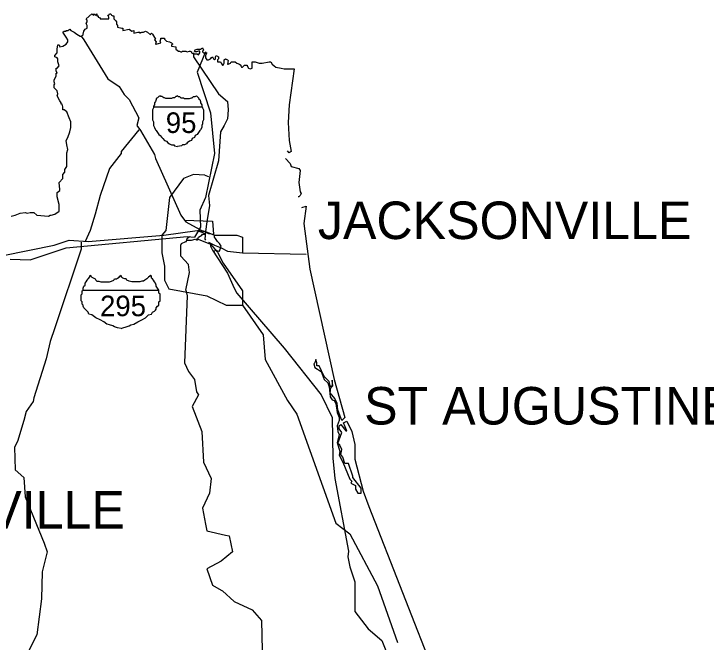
# Model space of a CAD drawing. Extents: x -820.2 to -798.1, y -2199.1 to -2182.2.
# Drawn here: x -806.07 to -805.24, y -2183.909 to -2183.155 of the extents above; entities that cross this region are included whole.
import ezdxf

# ---------------------------------------------------------------- set-up
doc = ezdxf.new("R2010")
doc.units = 0
for name, color, linetype in [('FLMap1', 7, 'Continuous'), ('FLMap2', 7, 'Continuous'), ('FLMap3', 7, 'Continuous'), ('TextMisc', 7, 'Continuous')]:
    doc.layers.add(name, color=color, linetype=linetype)

msp = doc.modelspace()

# ---------------------------------------------------------------- linework, layer by layer
at = {"layer": 'FLMap1'}
for p, q in [((-805.90286, -2183.26666), (-805.84382, -2183.26666)), ((-805.9872, -2183.48644), (-805.89641, -2183.48644))]:
    msp.add_line(p, q, dxfattribs=at)
for points in [[(-805.87408, -2183.25326), (-805.87508, -2183.25426), (-805.87607, -2183.25426), (-805.87756, -2183.25574), (-805.87855, -2183.25574), (-805.87954, -2183.25574), (-805.88103, -2183.25674), (-805.88202, -2183.25674), (-805.88351, -2183.25674), (-805.8845, -2183.25674), (-805.88698, -2183.25674), (-805.88798, -2183.25674), (-805.88946, -2183.25574), (-805.89046, -2183.25574), (-805.89294, -2183.25426), (-805.89393, -2183.25426), (-805.89492, -2183.25326), (-805.89641, -2183.25426), (-805.8979, -2183.25574), (-805.89939, -2183.25674), (-805.89939, -2183.25773), (-805.90038, -2183.26021), (-805.90137, -2183.2617), (-805.90137, -2183.26418), (-805.90286, -2183.26567), (-805.90286, -2183.26765), (-805.90385, -2183.27013), (-805.90385, -2183.27261), (-805.90385, -2183.27509), (-805.90385, -2183.27708), (-805.90385, -2183.27956), (-805.90385, -2183.28204), (-805.90286, -2183.28452), (-805.90286, -2183.287), (-805.90286, -2183.28899), (-805.90137, -2183.29147), (-805.90038, -2183.29395), (-805.89939, -2183.29494), (-805.8979, -2183.29742), (-805.89641, -2183.2999), (-805.89492, -2183.30089), (-805.89294, -2183.30337), (-805.89145, -2183.30437), (-805.88946, -2183.30685), (-805.88698, -2183.30784), (-805.8855, -2183.30982), (-805.88351, -2183.31081), (-805.88103, -2183.3123), (-805.87855, -2183.3123), (-805.87756, -2183.3133), (-805.87408, -2183.31429)], [(-805.87408, -2183.25326), (-805.8726, -2183.25426), (-805.8716, -2183.25426), (-805.87012, -2183.25574), (-805.86912, -2183.25574), (-805.86664, -2183.25574), (-805.86565, -2183.25674), (-805.86416, -2183.25674), (-805.86317, -2183.25674), (-805.86218, -2183.25674), (-805.86069, -2183.25674), (-805.8597, -2183.25674), (-805.85722, -2183.25574), (-805.85622, -2183.25574), (-805.85474, -2183.25426), (-805.85275, -2183.25426), (-805.85126, -2183.25326), (-805.85027, -2183.25426), (-805.84878, -2183.25574), (-805.84878, -2183.25674), (-805.84729, -2183.25773), (-805.8463, -2183.26021), (-805.8463, -2183.2617), (-805.84481, -2183.26418), (-805.84481, -2183.26567), (-805.84382, -2183.26765), (-805.84283, -2183.27013), (-805.84283, -2183.27261), (-805.84283, -2183.27509), (-805.84283, -2183.27708), (-805.84283, -2183.27956), (-805.84283, -2183.28204), (-805.84382, -2183.28452), (-805.84382, -2183.287), (-805.84481, -2183.28899), (-805.84481, -2183.29147), (-805.8463, -2183.29395), (-805.84729, -2183.29494), (-805.84878, -2183.29742), (-805.85027, -2183.2999), (-805.85275, -2183.30089), (-805.85374, -2183.30337), (-805.85622, -2183.30437), (-805.85722, -2183.30685), (-805.8597, -2183.30784), (-805.86218, -2183.30982), (-805.86317, -2183.31081), (-805.86565, -2183.3123), (-805.86813, -2183.3123), (-805.86912, -2183.3133), (-805.87408, -2183.31429)], [(-805.94156, -2183.53258), (-805.94602, -2183.53159), (-805.9495, -2183.5306), (-805.95148, -2183.52911), (-805.95545, -2183.52812), (-805.95892, -2183.52712), (-805.9624, -2183.52464), (-805.96686, -2183.52216), (-805.97182, -2183.51968), (-805.97678, -2183.51621), (-805.98026, -2183.51522), (-805.98125, -2183.51274), (-805.98224, -2183.51175), (-805.98373, -2183.51026), (-805.98472, -2183.50926), (-805.98621, -2183.50778), (-805.9872, -2183.50579), (-805.9872, -2183.5043), (-805.98819, -2183.50331), (-805.98819, -2183.50033), (-805.98968, -2183.49934), (-805.98968, -2183.49686), (-805.98968, -2183.49587), (-805.98968, -2183.49339), (-805.98968, -2183.4919), (-805.98819, -2183.49091), (-805.98819, -2183.48992), (-805.98819, -2183.48743), (-805.9872, -2183.48644), (-805.9872, -2183.48396), (-805.98621, -2183.48148), (-805.98472, -2183.48049), (-805.98472, -2183.47801), (-805.98373, -2183.47652), (-805.98224, -2183.47454), (-805.98125, -2183.47305), (-805.98026, -2183.47206), (-805.97877, -2183.46957), (-805.97877, -2183.46858), (-805.97777, -2183.46957), (-805.97678, -2183.47106), (-805.9743, -2183.47206), (-805.97281, -2183.47305), (-805.97182, -2183.47454), (-805.97083, -2183.47553), (-805.96835, -2183.47553), (-805.96587, -2183.47652), (-805.96339, -2183.47652), (-805.9624, -2183.47652), (-805.9614, -2183.47652), (-805.95892, -2183.47652), (-805.95743, -2183.47652), (-805.95545, -2183.47652), (-805.95297, -2183.47553), (-805.95049, -2183.47454), (-805.9495, -2183.47305), (-805.94702, -2183.47305), (-805.94602, -2183.47206), (-805.94404, -2183.47106), (-805.94305, -2183.46957), (-805.94156, -2183.46858)], [(-805.94156, -2183.53258), (-805.93957, -2183.53159), (-805.9356, -2183.5306), (-805.93213, -2183.52911), (-805.93015, -2183.52812), (-805.92618, -2183.52712), (-805.92171, -2183.52464), (-805.91675, -2183.52216), (-805.91229, -2183.51968), (-805.90881, -2183.51621), (-805.90534, -2183.51522), (-805.90385, -2183.51274), (-805.90137, -2183.51175), (-805.90038, -2183.51026), (-805.89939, -2183.50926), (-805.89939, -2183.50778), (-805.8979, -2183.50579), (-805.89641, -2183.5043), (-805.89641, -2183.50331), (-805.89641, -2183.50033), (-805.89492, -2183.49934), (-805.89492, -2183.49686), (-805.89492, -2183.49587), (-805.89492, -2183.49339), (-805.89492, -2183.4919), (-805.89492, -2183.49091), (-805.89641, -2183.48992), (-805.89641, -2183.48743), (-805.89641, -2183.48644), (-805.8979, -2183.48396), (-805.89939, -2183.48148), (-805.89939, -2183.48049), (-805.90038, -2183.47801), (-805.90137, -2183.47652), (-805.90286, -2183.47454), (-805.90385, -2183.47305), (-805.90534, -2183.47206), (-805.90534, -2183.46957), (-805.90633, -2183.46858), (-805.90733, -2183.46957), (-805.90881, -2183.47106), (-805.90981, -2183.47206), (-805.9108, -2183.47305), (-805.91328, -2183.47454), (-805.91477, -2183.47553), (-805.91675, -2183.47553), (-805.91923, -2183.47652), (-805.92022, -2183.47652), (-805.92271, -2183.47652), (-805.92419, -2183.47652), (-805.92519, -2183.47652), (-805.92767, -2183.47652), (-805.92866, -2183.47652), (-805.93213, -2183.47553), (-805.93461, -2183.47454), (-805.9356, -2183.47305), (-805.93709, -2183.47305), (-805.93957, -2183.47206), (-805.94057, -2183.47106), (-805.94156, -2183.46957), (-805.94156, -2183.46858)]]:
    msp.add_lwpolyline(points, dxfattribs=at)
at = {"layer": 'FLMap2'}
for points in [[(-805.98968, -2183.18182), (-805.98621, -2183.18629), (-805.95743, -2183.23292), (-805.94404, -2183.24235), (-805.93808, -2183.25178), (-805.93213, -2183.25773), (-805.92022, -2183.27956), (-805.92271, -2183.28899), (-805.91824, -2183.29494), (-805.90137, -2183.32371), (-805.90038, -2183.32868), (-805.87012, -2183.39664), (-805.86565, -2183.4026), (-805.83191, -2183.40359), (-805.83092, -2183.41947)], [(-805.85474, -2183.20167), (-805.85474, -2183.20663), (-805.82497, -2183.25078), (-805.81405, -2183.26021), (-805.81306, -2183.27013), (-805.81405, -2183.28105), (-805.81802, -2183.28899), (-805.82249, -2183.29643), (-805.82497, -2183.33116), (-805.83688, -2183.37283), (-805.83539, -2183.38474), (-805.83886, -2183.40458), (-805.84035, -2183.41599), (-805.84134, -2183.42542), (-805.84035, -2183.42641)], [(-805.73418, -2183.22102), (-805.74013, -2183.26418), (-805.74112, -2183.28551), (-805.74013, -2183.30685), (-805.73765, -2183.32024), (-805.74013, -2183.32173), (-805.74212, -2183.31925)], [(-805.92022, -2183.29395), (-805.94156, -2183.32024), (-805.94156, -2183.32272), (-805.95545, -2183.34058), (-805.96686, -2183.37283), (-805.97281, -2183.39516), (-805.97877, -2183.415), (-805.98472, -2183.4279)], [(-805.7446, -2183.32868), (-805.73864, -2183.33463), (-805.73765, -2183.3381), (-805.72822, -2183.34058), (-805.72822, -2183.34058), (-805.72674, -2183.34306), (-805.72822, -2183.35745), (-805.72674, -2183.36837), (-805.72574, -2183.37035), (-805.72674, -2183.37283), (-805.72822, -2183.37432), (-805.72922, -2183.37432)], [(-805.72475, -2183.38722), (-805.71979, -2183.38573), (-805.72227, -2183.40657), (-805.71533, -2183.46114), (-805.68605, -2183.59361), (-805.67315, -2183.63925), (-805.67663, -2183.64272)], [(-805.86565, -2183.4026), (-805.86416, -2183.40458), (-805.84729, -2183.41351), (-805.84481, -2183.415), (-805.84035, -2183.41599)], [(-806.2432, -2183.48743), (-806.2179, -2183.48148), (-806.18168, -2183.47801), (-806.11768, -2183.45419), (-806.1152, -2183.45122), (-806.02193, -2183.43237), (-806.00407, -2183.42641), (-805.98125, -2183.4279), (-805.89046, -2183.42046), (-805.85027, -2183.415), (-805.84035, -2183.41599), (-805.82943, -2183.42046), (-805.80264, -2183.42046), (-805.79619, -2183.42294), (-805.79619, -2183.43981)], [(-805.85027, -2183.415), (-805.84729, -2183.41599), (-805.84035, -2183.41847)], [(-805.86416, -2183.48644), (-805.8597, -2183.46511), (-805.86069, -2183.45568), (-805.87012, -2183.44576), (-805.87012, -2183.43237), (-805.86912, -2183.43038), (-805.86416, -2183.4279), (-805.86317, -2183.4279), (-805.86218, -2183.42443), (-805.8597, -2183.42195)], [(-805.86218, -2183.42641), (-805.85722, -2183.42641), (-805.85275, -2183.42542), (-805.85027, -2183.42641), (-805.84878, -2183.42294), (-805.84481, -2183.42046), (-805.84382, -2183.41947), (-805.84134, -2183.41947)], [(-805.84035, -2183.41699), (-805.83688, -2183.41847), (-805.83092, -2183.41947)], [(-805.83092, -2183.4408), (-805.82844, -2183.43832), (-805.82348, -2183.43981), (-805.8215, -2183.43385), (-805.82348, -2183.43038), (-805.82596, -2183.4279), (-805.82844, -2183.42443), (-805.82943, -2183.42294), (-805.82943, -2183.42046)], [(-805.98968, -2183.42889), (-805.98968, -2183.43733), (-806.02094, -2183.53159), (-806.02689, -2183.54796), (-806.03136, -2183.5688), (-806.04624, -2183.61544), (-806.04723, -2183.6199), (-806.05567, -2183.63181), (-806.05815, -2183.64272)], [(-805.83688, -2183.42889), (-805.82943, -2183.43237), (-805.8215, -2183.43584), (-805.81405, -2183.43981), (-805.79619, -2183.44179), (-805.71979, -2183.44328)], [(-805.83439, -2183.43137), (-805.83439, -2183.43385), (-805.83191, -2183.43832), (-805.81405, -2183.4661), (-805.80612, -2183.48396), (-805.80264, -2183.48992)], [(-805.79619, -2183.43981), (-805.79619, -2183.44179)], [(-805.86416, -2183.48644), (-805.86218, -2183.49339), (-805.86565, -2183.57376), (-805.86069, -2183.58418), (-805.85374, -2183.59361), (-805.85126, -2183.60849), (-805.84878, -2183.61196), (-805.85622, -2183.62585), (-805.84481, -2183.65612), (-805.84283, -2183.69283), (-805.8334, -2183.71218), (-805.83539, -2183.73004), (-805.84382, -2183.7479), (-805.84035, -2183.76725), (-805.83886, -2183.77519), (-805.81653, -2183.78015), (-805.81207, -2183.78114), (-805.8081, -2183.80049), (-805.8215, -2183.8114), (-805.83886, -2183.82083), (-805.83191, -2183.84018), (-805.8215, -2183.84613), (-805.82001, -2183.84713), (-805.80612, -2183.86002), (-805.78429, -2183.86995), (-805.77337, -2183.88285), (-805.77238, -2183.91857)], [(-805.80264, -2183.48992), (-805.74608, -2183.5559), (-805.70143, -2183.61196), (-805.68853, -2183.63925), (-805.68754, -2183.68787), (-805.68506, -2183.71218), (-805.66869, -2183.7995), (-805.66968, -2183.80644), (-805.6672, -2183.81835), (-805.66125, -2183.83621), (-805.66125, -2183.86399), (-805.66125, -2183.87193), (-805.64537, -2183.89277), (-805.629, -2183.90666), (-805.62404, -2183.91857)], [(-805.67663, -2183.64272), (-805.68159, -2183.62982), (-805.68258, -2183.62238), (-805.68506, -2183.61643), (-805.69101, -2183.60948), (-805.69002, -2183.60353), (-805.68754, -2183.60105), (-805.68853, -2183.5946), (-805.68853, -2183.60105), (-805.69002, -2183.60254), (-805.69101, -2183.60105), (-805.69201, -2183.59609), (-805.69796, -2183.59013), (-805.70391, -2183.57723), (-805.70689, -2183.57723), (-805.70689, -2183.57376), (-805.70788, -2183.56979), (-805.70937, -2183.57376), (-805.71036, -2183.57475), (-805.70937, -2183.57922), (-805.70143, -2183.58418), (-805.69796, -2183.59361), (-805.6935, -2183.59757), (-805.69201, -2183.60254), (-805.69101, -2183.61444), (-805.68853, -2183.61792), (-805.68605, -2183.61891), (-805.68407, -2183.62238), (-805.68258, -2183.6333), (-805.6801, -2183.63925), (-805.6801, -2183.64272)], [(-806.05815, -2183.64272), (-806.06609, -2183.66802), (-806.06956, -2183.67497), (-806.06857, -2183.70176), (-806.05815, -2183.71119), (-806.05666, -2183.7345), (-806.03384, -2183.79007), (-806.03036, -2183.80049), (-806.03632, -2183.8243), (-806.03731, -2183.85655), (-806.04277, -2183.89971), (-806.05815, -2183.93047)], [(-805.6801, -2183.64272), (-805.68258, -2183.64917), (-805.68159, -2183.65612), (-805.6801, -2183.65959), (-805.68258, -2183.66902), (-805.67911, -2183.67993), (-805.6801, -2183.6844), (-805.67564, -2183.69283), (-805.6672, -2183.71317), (-805.66472, -2183.71565), (-805.66621, -2183.71813), (-805.66026, -2183.72061), (-805.66026, -2183.72508), (-805.65777, -2183.73004), (-805.65381, -2183.73004), (-805.65381, -2183.72409), (-805.66373, -2183.71119), (-805.66373, -2183.7097), (-805.66869, -2183.69432), (-805.67315, -2183.69432), (-805.67564, -2183.68688), (-805.67812, -2183.6834), (-805.67663, -2183.67745), (-805.67911, -2183.67249), (-805.68159, -2183.6705), (-805.67663, -2183.65711), (-805.6801, -2183.65264), (-805.6801, -2183.64917), (-805.67812, -2183.64768), (-805.67216, -2183.65513), (-805.67067, -2183.65513), (-805.67464, -2183.6457), (-805.67067, -2183.64371), (-805.66472, -2183.65612), (-805.66125, -2183.6715), (-805.66125, -2183.68936), (-805.65132, -2183.72756), (-805.64438, -2183.74592)], [(-805.64438, -2183.74592), (-805.56351, -2183.9523)]]:
    msp.add_lwpolyline(points, dxfattribs=at)
at = {"layer": 'FLMap3'}
for points in [[(-805.98373, -2183.16644), (-805.98224, -2183.16446), (-805.98224, -2183.16347), (-805.98224, -2183.16247), (-805.98373, -2183.16099), (-805.97678, -2183.15503), (-805.9743, -2183.15652), (-805.9743, -2183.15503), (-805.97182, -2183.15652), (-805.97083, -2183.15503), (-805.97083, -2183.15652), (-805.97083, -2183.15751), (-805.96934, -2183.15751), (-805.96934, -2183.159), (-805.96686, -2183.15999), (-805.96686, -2183.16099), (-805.9624, -2183.16099), (-805.95743, -2183.16099), (-805.95644, -2183.16099), (-805.95644, -2183.15999), (-805.95644, -2183.159), (-805.95743, -2183.15652), (-805.95644, -2183.15652), (-805.95545, -2183.15503), (-805.95396, -2183.15503), (-805.95297, -2183.15652), (-805.95148, -2183.15751), (-805.95049, -2183.15751), (-805.95049, -2183.16099), (-805.94801, -2183.16347), (-805.94702, -2183.16446), (-805.94702, -2183.16743), (-805.94602, -2183.16892), (-805.94602, -2183.17091), (-805.94057, -2183.1724), (-805.93957, -2183.1724), (-805.93957, -2183.17488), (-805.93213, -2183.17339), (-805.92866, -2183.17587), (-805.92618, -2183.17488), (-805.92618, -2183.17587), (-805.92618, -2183.17686), (-805.92618, -2183.17835), (-805.92171, -2183.17686), (-805.91923, -2183.17686), (-805.91923, -2183.17835), (-805.91675, -2183.17686), (-805.91477, -2183.17686), (-805.91229, -2183.17587), (-805.90981, -2183.17686), (-805.90633, -2183.18033), (-805.90633, -2183.18033), (-805.90633, -2183.17934), (-805.90534, -2183.17835), (-805.90534, -2183.17835), (-805.90385, -2183.17934), (-805.90038, -2183.1853), (-805.90137, -2183.18629), (-805.89939, -2183.18877), (-805.90038, -2183.19125), (-805.89939, -2183.19125), (-805.89393, -2183.18976), (-805.89393, -2183.18976), (-805.89492, -2183.18778), (-805.89393, -2183.1853), (-805.89393, -2183.1843), (-805.89294, -2183.1843), (-805.88946, -2183.1843), (-805.88946, -2183.1853), (-805.88698, -2183.18778), (-805.88351, -2183.18877), (-805.88103, -2183.18976), (-805.87954, -2183.19125), (-805.88103, -2183.19224), (-805.88103, -2183.19373), (-805.87607, -2183.19472), (-805.87607, -2183.19571), (-805.87607, -2183.1972), (-805.87607, -2183.1972), (-805.8726, -2183.19968), (-805.8716, -2183.19968), (-805.87012, -2183.20068), (-805.86912, -2183.20068), (-805.86813, -2183.19968), (-805.86565, -2183.19968), (-805.86416, -2183.19968), (-805.86218, -2183.20068), (-805.8597, -2183.19968), (-805.85871, -2183.19968), (-805.85722, -2183.20068), (-805.85722, -2183.20167), (-805.85474, -2183.20316), (-805.85275, -2183.20316), (-805.85027, -2183.20316)], [(-806.0254, -2183.39664), (-806.02094, -2183.39516), (-806.01598, -2183.39168), (-806.01598, -2183.38821), (-806.01598, -2183.38374), (-806.01846, -2183.37432), (-806.01846, -2183.36936), (-806.01498, -2183.36688), (-806.01498, -2183.36588), (-806.01598, -2183.35745), (-806.01151, -2183.35249), (-806.01151, -2183.34753), (-806.00903, -2183.34505), (-806.00903, -2183.34157), (-806.00655, -2183.3381), (-806.00655, -2183.33314), (-806.00655, -2183.32768), (-806.00655, -2183.32173), (-806.00556, -2183.31776), (-806.00655, -2183.3123), (-806.00754, -2183.30685), (-806.00556, -2183.30337), (-806.00308, -2183.29643), (-806.00208, -2183.29147), (-806.00208, -2183.28452), (-806.00407, -2183.27956), (-806.00655, -2183.27261), (-806.01002, -2183.27013), (-806.01151, -2183.27013), (-806.01151, -2183.26666), (-806.0125, -2183.26319), (-806.0135, -2183.26319), (-806.0135, -2183.2617), (-806.01498, -2183.25922), (-806.01846, -2183.25326), (-806.01746, -2183.25078), (-806.01846, -2183.24731), (-806.02193, -2183.24384), (-806.02193, -2183.24036), (-806.02094, -2183.23888), (-806.02193, -2183.2364), (-806.02193, -2183.23441), (-806.01945, -2183.22945), (-806.01945, -2183.22598), (-806.01846, -2183.22598), (-806.01945, -2183.2235), (-806.01945, -2183.22102), (-806.01945, -2183.22002), (-806.01846, -2183.22002), (-806.01598, -2183.21754), (-806.01746, -2183.21258), (-806.01746, -2183.20911), (-806.01846, -2183.20762), (-806.02094, -2183.20663), (-806.02094, -2183.20514), (-806.01846, -2183.20167), (-806.01846, -2183.20068), (-806.01846, -2183.19819), (-806.01846, -2183.19819), (-806.01846, -2183.1972), (-806.01746, -2183.19224), (-806.01598, -2183.19224), (-806.01498, -2183.19472), (-806.01151, -2183.19373), (-806.00754, -2183.19125), (-806.00556, -2183.18877), (-806.00556, -2183.18629), (-806.00754, -2183.18281), (-806.01002, -2183.17934), (-806.01151, -2183.17686), (-806.01002, -2183.17587), (-806.00754, -2183.17587), (-806.00754, -2183.17488), (-806.00556, -2183.17488), (-806.00556, -2183.17488), (-806.00308, -2183.17339), (-806.00208, -2183.17488), (-805.99812, -2183.17686), (-805.99464, -2183.17934), (-805.99067, -2183.18182), (-805.98968, -2183.18182), (-805.9872, -2183.18033), (-805.9872, -2183.17934), (-805.98621, -2183.17587), (-805.98472, -2183.17339), (-805.98224, -2183.1724), (-805.98224, -2183.17091), (-805.98224, -2183.16892), (-805.98373, -2183.16644)], [(-805.85027, -2183.20316), (-805.84878, -2183.20415), (-805.84729, -2183.20167), (-805.84729, -2183.19968), (-805.84878, -2183.19968), (-805.85126, -2183.20068), (-805.85275, -2183.20068), (-805.85374, -2183.19968), (-805.85275, -2183.19819), (-805.85027, -2183.1972), (-805.8463, -2183.1972), (-805.84382, -2183.19571), (-805.84283, -2183.19819), (-805.84382, -2183.19968), (-805.84382, -2183.20068), (-805.84283, -2183.20167), (-805.84134, -2183.20167), (-805.84035, -2183.20167), (-805.83886, -2183.20167), (-805.84035, -2183.20514), (-805.84035, -2183.20762), (-805.83886, -2183.2101), (-805.83688, -2183.2101), (-805.83439, -2183.20911), (-805.8334, -2183.20762), (-805.83191, -2183.20663), (-805.83092, -2183.20911), (-805.82943, -2183.2101), (-805.82844, -2183.20911), (-805.82844, -2183.20663), (-805.82745, -2183.20514), (-805.82497, -2183.20663), (-805.82497, -2183.20911), (-805.82596, -2183.2101), (-805.82596, -2183.21258), (-805.82497, -2183.21258), (-805.82249, -2183.21258), (-805.8215, -2183.21407), (-805.82001, -2183.21655), (-805.81902, -2183.21655), (-805.81802, -2183.21407), (-805.81802, -2183.2101), (-805.81653, -2183.20911), (-805.81405, -2183.2101), (-805.81306, -2183.21109), (-805.81405, -2183.21556), (-805.81306, -2183.21556), (-805.81058, -2183.21407), (-805.80959, -2183.21258), (-805.80711, -2183.21258), (-805.80463, -2183.21258), (-805.80264, -2183.21407), (-805.79967, -2183.21556), (-805.79818, -2183.21655), (-805.79818, -2183.21754), (-805.79719, -2183.21903), (-805.79619, -2183.21903), (-805.79371, -2183.21655), (-805.79222, -2183.21655), (-805.79024, -2183.21655), (-805.79024, -2183.21754), (-805.78875, -2183.22002), (-805.78677, -2183.22102), (-805.78429, -2183.22002), (-805.78429, -2183.21903), (-805.78429, -2183.21556), (-805.78429, -2183.21407), (-805.78429, -2183.21258), (-805.78081, -2183.21258), (-805.77585, -2183.21407), (-805.77238, -2183.21407), (-805.76395, -2183.21258), (-805.76196, -2183.21258), (-805.76047, -2183.21556), (-805.75799, -2183.21754), (-805.75601, -2183.21903), (-805.74956, -2183.22002), (-805.74608, -2183.22102), (-805.73418, -2183.22102)], [(-805.84035, -2183.20068), (-805.85027, -2183.22499), (-805.83439, -2183.27361), (-805.82943, -2183.32272), (-805.84035, -2183.37531), (-805.84729, -2183.39069), (-805.8463, -2183.41103), (-805.85374, -2183.42294)], [(-805.84134, -2183.34852), (-805.85474, -2183.34753), (-805.86664, -2183.35249), (-805.88351, -2183.37531), (-805.88798, -2183.415), (-805.89294, -2183.42046), (-805.89294, -2183.44179), (-805.88946, -2183.45767), (-805.88946, -2183.47454), (-805.8845, -2183.48495), (-805.83886, -2183.49339), (-805.81554, -2183.5043), (-805.79619, -2183.5043)], [(-805.84134, -2183.34852), (-805.83688, -2183.35001)], [(-806.07353, -2183.39764), (-806.06857, -2183.39664), (-806.06261, -2183.39416), (-806.05666, -2183.39317), (-806.05418, -2183.39416), (-806.05071, -2183.39317), (-806.04624, -2183.39317), (-806.04277, -2183.39664), (-806.02888, -2183.39764), (-806.02689, -2183.39664), (-806.0254, -2183.39664)], [(-806.07452, -2183.44923), (-806.05071, -2183.45023), (-806.00754, -2183.43584), (-805.86218, -2183.42195), (-805.85374, -2183.42294)], [(-805.85126, -2183.42443), (-805.83439, -2183.43137), (-805.82596, -2183.4408), (-805.81902, -2183.45419), (-805.79619, -2183.48743), (-805.79619, -2183.5043), (-805.77139, -2183.54002), (-805.76891, -2183.56979), (-805.74212, -2183.61891), (-805.7307, -2183.63528), (-805.68407, -2183.76576), (-805.6672, -2183.77866), (-805.63396, -2183.84117), (-805.61015, -2183.90914)]]:
    msp.add_lwpolyline(points, dxfattribs=at)

# ---------------------------------------------------------------- texts
at = {"layer": 'TextMisc'}
for s, height, p in [('95', 0.024695, (-805.88799, -2183.29792)), ('JACKSONVILLE', 0.045, (-805.70553, -2183.42517)), ('295', 0.024695, (-805.96686, -2183.5177)), ('ST AUGUSTINE', 0.045, (-805.65009, -2183.64761)), ('GAINESVILLE', 0.045, (-806.32836, -2183.77248))]:
    msp.add_text(s, height=height, dxfattribs=at).set_placement(p)

doc.saveas('drawing.dxf')
